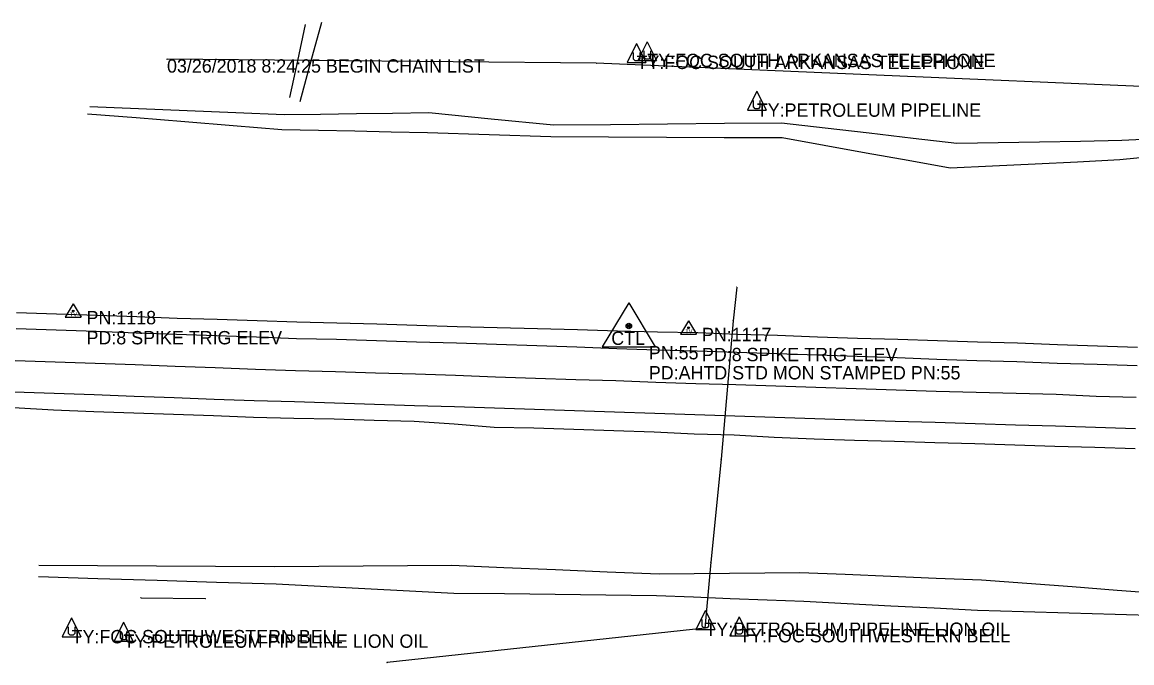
# Model space of a CAD drawing. Extents: x 976456 to 985170, y 1525951 to 1527080.
# Drawn here: x 976999.9 to 977415.4, y 1526416.8 to 1526656.5 of the extents above; entities that cross this region are included whole.
import ezdxf

# ---------------------------------------------------------------- set-up
doc = ezdxf.new("R2010")
doc.units = 0
for name, color, linetype in [('S_DITCHLINE', 7, 'Continuous'), ('S_EDGE_PAVEMENT', 7, 'Continuous'), ('S_FENCE', 7, 'Continuous'), ('S_FENCE_ANNOT', 7, 'Continuous'), ('S_FIBER_OPTIC_CABLE', 7, 'Continuous'), ('S_GAS_UTILITIES', 7, 'Continuous'), ('S_MSC_PT_SYM', 7, 'Continuous'), ('S_PAVEMENT_CROWN', 7, 'Continuous'), ('S_PRIMARY_CTL', 7, 'Continuous'), ('S_PRIMARY_CTL_ANNOT', 7, 'Continuous'), ('S_SECONDARY_CTL', 7, 'Continuous'), ('S_SECONDARY_CTL_ANNOT', 7, 'Continuous'), ('S_SHOULDER', 7, 'Continuous'), ('S_UNDERGROUND_CABLE', 7, 'Continuous'), ('S_UTILITY_POLE_ANNOT', 7, 'Continuous'), ('S_UTL_PT_SYM', 7, 'Continuous')]:
    doc.layers.add(name, color=color, linetype=linetype)

msp = doc.modelspace()

# ---------------------------------------------------------------- linework, layer by layer
at = {"layer": 'S_DITCHLINE'}
for points in [[(977105.93, 1526655.71), (977102.97, 1526642.03), (977100.01, 1526628.36)], [(977104, 1526626.89), (977108.07, 1526641.71), (977112.14, 1526656.53)], [(977427.49, 1526606.7), (977410.9, 1526604.96), (977395.02, 1526604.2), (977379.13, 1526603.44), (977363.24, 1526602.69), (977347.36, 1526601.93), (977331.62, 1526604.74), (977315.89, 1526607.56), (977300.16, 1526610.38), (977284.42, 1526613.2), (977262.78, 1526613.31), (977241.14, 1526613.43), (977219.49, 1526613.54), (977197.85, 1526613.66), (977174.77, 1526614.38), (977151.69, 1526615.11), (977138.06, 1526615.4), (977124.44, 1526615.7), (977110.82, 1526616), (977097.19, 1526616.29), (977078.99, 1526617.75), (977060.78, 1526619.21), (977042.58, 1526620.68), (977024.37, 1526622.14)], [(977427.48, 1526612.95), (977411.59, 1526612.21), (977396.17, 1526611.94), (977380.75, 1526611.67), (977365.33, 1526611.4), (977349.91, 1526611.12), (977333.47, 1526613.04), (977317.04, 1526614.95), (977300.6, 1526616.86), (977284.16, 1526618.77), (977262.83, 1526618.58), (977241.49, 1526618.38), (977220.16, 1526618.18), (977198.83, 1526617.99), (977175.5, 1526620.3), (977152.17, 1526622.62), (977138.64, 1526622.42), (977125.11, 1526622.22), (977111.58, 1526622.02), (977098.05, 1526621.81), (977079.87, 1526622.57), (977061.69, 1526623.32), (977043.5, 1526624.07), (977025.32, 1526624.82)], [(977426.88, 1526442.63), (977409.94, 1526443.9), (977393, 1526445.17), (977376.05, 1526446.43), (977359.11, 1526447.7), (977342.11, 1526448.39), (977325.11, 1526449.09), (977308.11, 1526449.79), (977291.11, 1526450.48), (977277.93, 1526450.35), (977264.76, 1526450.21), (977251.58, 1526450.08), (977238.41, 1526449.94), (977219.01, 1526450.75), (977199.61, 1526451.56), (977180.21, 1526452.37), (977160.8, 1526453.18), (977144.2, 1526453.06), (977127.59, 1526452.94), (977110.98, 1526452.82), (977094.38, 1526452.7), (977072.32, 1526452.83), (977050.26, 1526452.96), (977028.2, 1526453.08), (977006.14, 1526453.21)], [(977426.27, 1526434.42), (977409.1, 1526434.91), (977391.93, 1526435.4), (977374.76, 1526435.89), (977357.59, 1526436.38), (977341.35, 1526437.21), (977325.1, 1526438.03), (977308.85, 1526438.86), (977292.6, 1526439.69), (977278.82, 1526440.23), (977265.03, 1526440.78), (977251.24, 1526441.32), (977237.46, 1526441.87), (977218.48, 1526442.09), (977199.49, 1526442.32), (977180.51, 1526442.54), (977161.53, 1526442.76), (977144.9, 1526443.61), (977128.26, 1526444.47), (977111.62, 1526445.32), (977094.99, 1526446.17), (977072.75, 1526446.86), (977050.52, 1526447.56), (977028.28, 1526448.25), (977006.05, 1526448.94)]]:
    msp.add_lwpolyline(points, dxfattribs=at)
at = {"layer": 'S_EDGE_PAVEMENT'}
for points in [[(976997.66, 1526541.9), (977012.66, 1526541.41), (977027.65, 1526540.95), (977042.64, 1526540.3), (977042.64, 1526540.3), (977042.64, 1526540.3), (977057.72, 1526539.72), (977072.72, 1526539.29), (977087.71, 1526538.75), (977102.58, 1526538.2), (977117.58, 1526537.85), (977132.57, 1526537.4), (977147.56, 1526536.93), (977162.56, 1526536.48), (977177.55, 1526536.07), (977192.62, 1526535.54), (977192.62, 1526535.54), (977207.61, 1526535), (977222.6, 1526534.4), (977237.59, 1526533.95), (977252.59, 1526533.5), (977267.53, 1526532.98), (977282.52, 1526532.5), (977297.51, 1526532.01), (977312.5, 1526531.51), (977327.49, 1526531.03), (977342.39, 1526530.45), (977342.39, 1526530.45), (977357.39, 1526529.94), (977372.38, 1526529.54), (977387.37, 1526528.96), (977402.36, 1526528.58), (977417.36, 1526528.07)], [(976996.92, 1526518.21), (977011.91, 1526517.74), (977026.9, 1526517.15), (977041.89, 1526516.56), (977056.8, 1526516.04), (977071.79, 1526515.5), (977086.78, 1526514.91), (977101.86, 1526514.53), (977116.86, 1526514.09), (977131.85, 1526513.55), (977146.84, 1526513.1), (977161.84, 1526512.66), (977176.83, 1526512.17), (977191.76, 1526511.68), (977206.75, 1526511.16), (977206.75, 1526511.16), (977221.74, 1526510.68), (977236.74, 1526510.26), (977251.73, 1526509.72), (977251.73, 1526509.72), (977266.76, 1526509.26), (977281.75, 1526508.76), (977296.74, 1526508.27), (977311.73, 1526507.76), (977326.73, 1526507.26), (977341.79, 1526506.8), (977356.78, 1526506.35), (977371.78, 1526505.89), (977386.77, 1526505.41), (977386.77, 1526505.41), (977386.77, 1526505.41), (977401.76, 1526505.02), (977416.76, 1526504.51)]]:
    msp.add_lwpolyline(points, dxfattribs=at)
at = {"layer": 'S_FENCE'}
for p, q in [((977214.88, 1526641.2), (977054.17, 1526642.65)), ((977429.97, 1526631.95), (977214.88, 1526641.2))]:
    msp.add_line(p, q, dxfattribs=at)
at = {"layer": 'S_FIBER_OPTIC_CABLE'}
msp.add_line((977044.42, 1526441.15), (977068.48, 1526440.82), dxfattribs=at)
at = {"layer": 'S_GAS_UTILITIES'}
for p, q in [((977267.46, 1526557.36), (977266.17, 1526544.82)), ((977266.17, 1526544.82), (977261.62, 1526492.96)), ((977261.62, 1526492.96), (977257.75, 1526454.41)), ((977257.75, 1526454.41), (977255.52, 1526429.71)), ((977255.52, 1526429.71), (977136.53, 1526416.84))]:
    msp.add_line(p, q, dxfattribs=at)
at = {"layer": 'S_MSC_PT_SYM'}
for points in [[(977054.17, 1526642.65), (977054.17, 1526642.7), (977054.17, 1526642.65), (977054.12, 1526642.65), (977054.17, 1526642.65), (977054.17, 1526642.6), (977054.17, 1526642.65), (977054.22, 1526642.65)], [(977214.88, 1526641.2), (977214.88, 1526641.25), (977214.88, 1526641.2), (977214.83, 1526641.2), (977214.88, 1526641.2), (977214.88, 1526641.15), (977214.88, 1526641.2), (977214.93, 1526641.2)]]:
    msp.add_lwpolyline(points, dxfattribs=at)
at = {"layer": 'S_PAVEMENT_CROWN'}
msp.add_lwpolyline([(976997.29, 1526529.9), (977012.28, 1526529.43), (977027.27, 1526528.94), (977042.26, 1526528.45), (977057.26, 1526527.8), (977072.25, 1526527.24), (977087.24, 1526526.65), (977102.22, 1526526.21), (977117.21, 1526525.81), (977132.21, 1526525.36), (977147.2, 1526524.9), (977162.19, 1526524.45), (977177.18, 1526523.85), (977192.18, 1526523.35), (977207.17, 1526522.8), (977222.17, 1526522.39), (977237.16, 1526521.85), (977252.15, 1526521.37), (977267.14, 1526520.95), (977282.13, 1526520.42), (977297.12, 1526519.93), (977312.11, 1526519.44), (977327.1, 1526518.96), (977342.09, 1526518.5), (977357.08, 1526518.12), (977372.08, 1526517.7), (977387.07, 1526517.29), (977402.06, 1526516.56), (977417.05, 1526516.17)], dxfattribs=at)
at = {"layer": 'S_PRIMARY_CTL'}
for p, q in [((977227.06, 1526551.54), (977217.03, 1526535.03)), ((977227.06, 1526551.54), (977236.89, 1526535.03)), ((977217.03, 1526535.03), (977236.89, 1526535.03))]:
    msp.add_line(p, q, dxfattribs=at)
for radius in [1.04, 0.609, 0.344]:
    msp.add_circle((977227.06, 1526542.84), radius, dxfattribs=at)
at = {"layer": 'S_SECONDARY_CTL'}
for p, q in [((977019.04, 1526551.07), (977016.03, 1526546.11)), ((977019.04, 1526551.07), (977021.99, 1526546.11)), ((977016.03, 1526546.11), (977021.99, 1526546.11)), ((977249.43, 1526544.76), (977246.42, 1526539.81)), ((977249.43, 1526544.76), (977252.38, 1526539.81)), ((977246.42, 1526539.81), (977252.38, 1526539.81))]:
    msp.add_line(p, q, dxfattribs=at)
for centre, radius in [((977019.04, 1526548.46), 0.311), ((977019.04, 1526548.46), 0.183), ((977019.04, 1526548.46), 0.103), ((977249.43, 1526542.15), 0.311), ((977249.43, 1526542.15), 0.183), ((977249.43, 1526542.15), 0.103)]:
    msp.add_circle(centre, radius, dxfattribs=at)
at = {"layer": 'S_SHOULDER'}
for points in [[(976997.85, 1526547.87), (977012.84, 1526547.38), (977027.84, 1526546.92), (977042.83, 1526546.38), (977057.96, 1526545.79), (977072.96, 1526545.37), (977087.95, 1526544.92), (977102.77, 1526544.36), (977117.76, 1526544.06), (977132.76, 1526543.61), (977147.75, 1526543.14), (977162.74, 1526542.69), (977177.74, 1526542.28), (977192.85, 1526541.94), (977207.85, 1526541.55), (977222.84, 1526541.05), (977237.84, 1526540.71), (977252.83, 1526540.35), (977267.75, 1526539.83), (977282.74, 1526539.34), (977297.73, 1526538.83), (977312.72, 1526538.33), (977327.72, 1526537.95), (977342.57, 1526537.37), (977357.56, 1526536.88), (977372.56, 1526536.48), (977387.55, 1526535.87), (977402.54, 1526535.38), (977417.53, 1526534.88)], [(976996.74, 1526512.29), (977011.72, 1526511.44), (977026.71, 1526510.88), (977041.7, 1526510.31), (977056.56, 1526509.8), (977071.55, 1526509.29), (977086.54, 1526508.71), (977101.69, 1526508.38), (977116.69, 1526508.13), (977131.68, 1526507.65), (977146.67, 1526507.18), (977161.65, 1526506.24), (977176.62, 1526505), (977191.52, 1526504.71), (977206.51, 1526504.19), (977221.5, 1526503.71), (977236.49, 1526503.19), (977251.48, 1526502.53), (977266.54, 1526502.12), (977281.52, 1526501.19), (977296.5, 1526500.6), (977311.5, 1526500.15), (977326.49, 1526499.74), (977341.6, 1526499.22), (977356.6, 1526498.85), (977371.59, 1526498.34), (977386.58, 1526497.86), (977401.58, 1526497.45), (977416.57, 1526496.94)]]:
    msp.add_lwpolyline(points, dxfattribs=at)
at = {"layer": 'S_UNDERGROUND_CABLE'}
for p, q in [((977229.96, 1526648.54), (977226.44, 1526641.45)), ((977229.96, 1526648.54), (977233.45, 1526641.45)), ((977233.97, 1526649.24), (977230.44, 1526642.15)), ((977233.97, 1526649.24), (977237.45, 1526642.15)), ((977228.76, 1526642.69), (977228.76, 1526645.13)), ((977229.38, 1526642.03), (977228.76, 1526642.69)), ((977230.58, 1526642.03), (977229.38, 1526642.03)), ((977230.44, 1526642.15), (977237.45, 1526642.15)), ((977231.12, 1526642.69), (977230.58, 1526642.03)), ((977231.12, 1526645.13), (977231.12, 1526642.69)), ((977232.76, 1526643.39), (977232.76, 1526645.83)), ((977233.38, 1526642.73), (977232.76, 1526643.39)), ((977234.59, 1526642.73), (977233.38, 1526642.73)), ((977235.13, 1526643.39), (977234.59, 1526642.73)), ((977235.13, 1526645.83), (977235.13, 1526643.39)), ((977226.44, 1526641.45), (977233.45, 1526641.45)), ((977274.97, 1526630.66), (977271.44, 1526623.57)), ((977274.97, 1526630.66), (977278.45, 1526623.57)), ((977273.76, 1526624.81), (977273.76, 1526627.25)), ((977276.13, 1526627.25), (977276.13, 1526624.81)), ((977271.44, 1526623.57), (977278.45, 1526623.57)), ((977274.38, 1526624.15), (977273.76, 1526624.81)), ((977275.59, 1526624.15), (977274.38, 1526624.15)), ((977276.13, 1526624.81), (977275.59, 1526624.15)), ((977255.73, 1526436.39), (977252.2, 1526429.3)), ((977255.73, 1526436.39), (977259.22, 1526429.3)), ((977018.46, 1526433.61), (977014.94, 1526426.52)), ((977017.26, 1526427.76), (977017.26, 1526430.2)), ((977018.46, 1526433.61), (977021.95, 1526426.52)), ((977019.63, 1526430.2), (977019.63, 1526427.76)), ((977037.9, 1526431.94), (977034.37, 1526424.85)), ((977037.9, 1526431.94), (977041.39, 1526424.85)), ((977254.53, 1526430.54), (977254.53, 1526432.98)), ((977255.15, 1526429.88), (977254.53, 1526430.54)), ((977256.89, 1526430.54), (977256.35, 1526429.88)), ((977256.89, 1526432.98), (977256.89, 1526430.54)), ((977268.42, 1526433.97), (977264.9, 1526426.88)), ((977267.22, 1526428.12), (977267.22, 1526430.56)), ((977268.42, 1526433.97), (977271.91, 1526426.88)), ((977269.58, 1526430.56), (977269.58, 1526428.12)), ((977014.94, 1526426.52), (977021.95, 1526426.52)), ((977017.88, 1526427.1), (977017.26, 1526427.76)), ((977019.08, 1526427.1), (977017.88, 1526427.1)), ((977019.63, 1526427.76), (977019.08, 1526427.1)), ((977036.7, 1526426.09), (977036.7, 1526428.53)), ((977037.32, 1526425.43), (977036.7, 1526426.09)), ((977039.06, 1526426.09), (977038.52, 1526425.43)), ((977039.06, 1526428.53), (977039.06, 1526426.09)), ((977252.2, 1526429.3), (977259.22, 1526429.3)), ((977256.35, 1526429.88), (977255.15, 1526429.88)), ((977264.9, 1526426.88), (977271.91, 1526426.88)), ((977267.84, 1526427.46), (977267.22, 1526428.12)), ((977269.04, 1526427.46), (977267.84, 1526427.46)), ((977269.58, 1526428.12), (977269.04, 1526427.46)), ((977034.37, 1526424.85), (977041.39, 1526424.85)), ((977038.52, 1526425.43), (977037.32, 1526425.43))]:
    msp.add_line(p, q, dxfattribs=at)
at = {"layer": 'S_UTL_PT_SYM'}
for points in [[(977267.46, 1526557.36), (977267.46, 1526557.41), (977267.46, 1526557.36), (977267.41, 1526557.36), (977267.46, 1526557.36), (977267.46, 1526557.31), (977267.46, 1526557.36), (977267.51, 1526557.36)], [(977266.17, 1526544.82), (977266.17, 1526544.87), (977266.17, 1526544.82), (977266.12, 1526544.82), (977266.17, 1526544.82), (977266.17, 1526544.77), (977266.17, 1526544.82), (977266.22, 1526544.82)], [(977261.62, 1526492.96), (977261.62, 1526493.01), (977261.62, 1526492.96), (977261.57, 1526492.96), (977261.62, 1526492.96), (977261.62, 1526492.91), (977261.62, 1526492.96), (977261.67, 1526492.96)], [(977257.75, 1526454.41), (977257.75, 1526454.46), (977257.75, 1526454.41), (977257.7, 1526454.41), (977257.75, 1526454.41), (977257.75, 1526454.36), (977257.75, 1526454.41), (977257.8, 1526454.41)], [(977044.42, 1526441.15), (977044.42, 1526441.2), (977044.42, 1526441.15), (977044.37, 1526441.15), (977044.42, 1526441.15), (977044.42, 1526441.1), (977044.42, 1526441.15), (977044.47, 1526441.15)], [(977068.48, 1526440.82), (977068.48, 1526440.87), (977068.48, 1526440.82), (977068.43, 1526440.82), (977068.48, 1526440.82), (977068.48, 1526440.77), (977068.48, 1526440.82), (977068.53, 1526440.82)], [(977255.52, 1526429.71), (977255.52, 1526429.76), (977255.52, 1526429.71), (977255.47, 1526429.71), (977255.52, 1526429.71), (977255.52, 1526429.66), (977255.52, 1526429.71), (977255.57, 1526429.71)], [(977136.53, 1526416.84), (977136.53, 1526416.89), (977136.53, 1526416.84), (977136.48, 1526416.84), (977136.53, 1526416.84), (977136.53, 1526416.79), (977136.53, 1526416.84), (977136.58, 1526416.84)]]:
    msp.add_lwpolyline(points, dxfattribs=at)

# ---------------------------------------------------------------- texts
at = {"layer": 'S_FENCE_ANNOT'}
msp.add_text('03/26/2018 8:24:25 BEGIN CHAIN LIST', height=5, dxfattribs=at).set_placement((977054.17, 1526637.65))
at = {"layer": 'S_PRIMARY_CTL'}
msp.add_text('CTL', height=5, rotation=360, dxfattribs=at).set_placement((977220.48, 1526535.77))
at = {"layer": 'S_PRIMARY_CTL_ANNOT'}
for s, p in [('PN:55', (977234.56, 1526530.34)), ('PD:AHTD STD MON STAMPED PN:55', (977234.56, 1526522.84))]:
    msp.add_text(s, height=5, dxfattribs=at).set_placement(p)
at = {"layer": 'S_SECONDARY_CTL'}
for p in [(977017.84, 1526546.45), (977248.23, 1526540.14)]:
    msp.add_text('TV', height=1.5, rotation=360, dxfattribs=at).set_placement(p)
at = {"layer": 'S_SECONDARY_CTL_ANNOT'}
for s, p in [('PN:1118', (977024.04, 1526543.46)), ('PD:8 SPIKE TRIG ELEV', (977024.04, 1526535.96)), ('PN:1117', (977254.43, 1526537.15)), ('PD:8 SPIKE TRIG ELEV', (977254.43, 1526529.65))]:
    msp.add_text(s, height=5, dxfattribs=at).set_placement(p)
at = {"layer": 'S_UTILITY_POLE_ANNOT'}
for s, p in [('TY:FOC SOUTH ARKANSAS TELEPHONE', (977229.96, 1526639)), ('TY:FOC SOUTH ARKANSAS TELEPHONE', (977233.97, 1526639.71)), ('TY:PETROLEUM PIPELINE', (977274.97, 1526621.13)), ('TY:PETROLEUM PIPELINE LION OIL', (977255.73, 1526426.86)), ('TY:FOC SOUTHWESTERN BELL', (977018.46, 1526424.07)), ('TY:PETROLEUM PIPELINE LION OIL', (977037.9, 1526422.4)), ('TY:FOC SOUTHWESTERN BELL', (977268.42, 1526424.44))]:
    msp.add_text(s, height=5, dxfattribs=at).set_placement(p)

doc.saveas('drawing.dxf')
